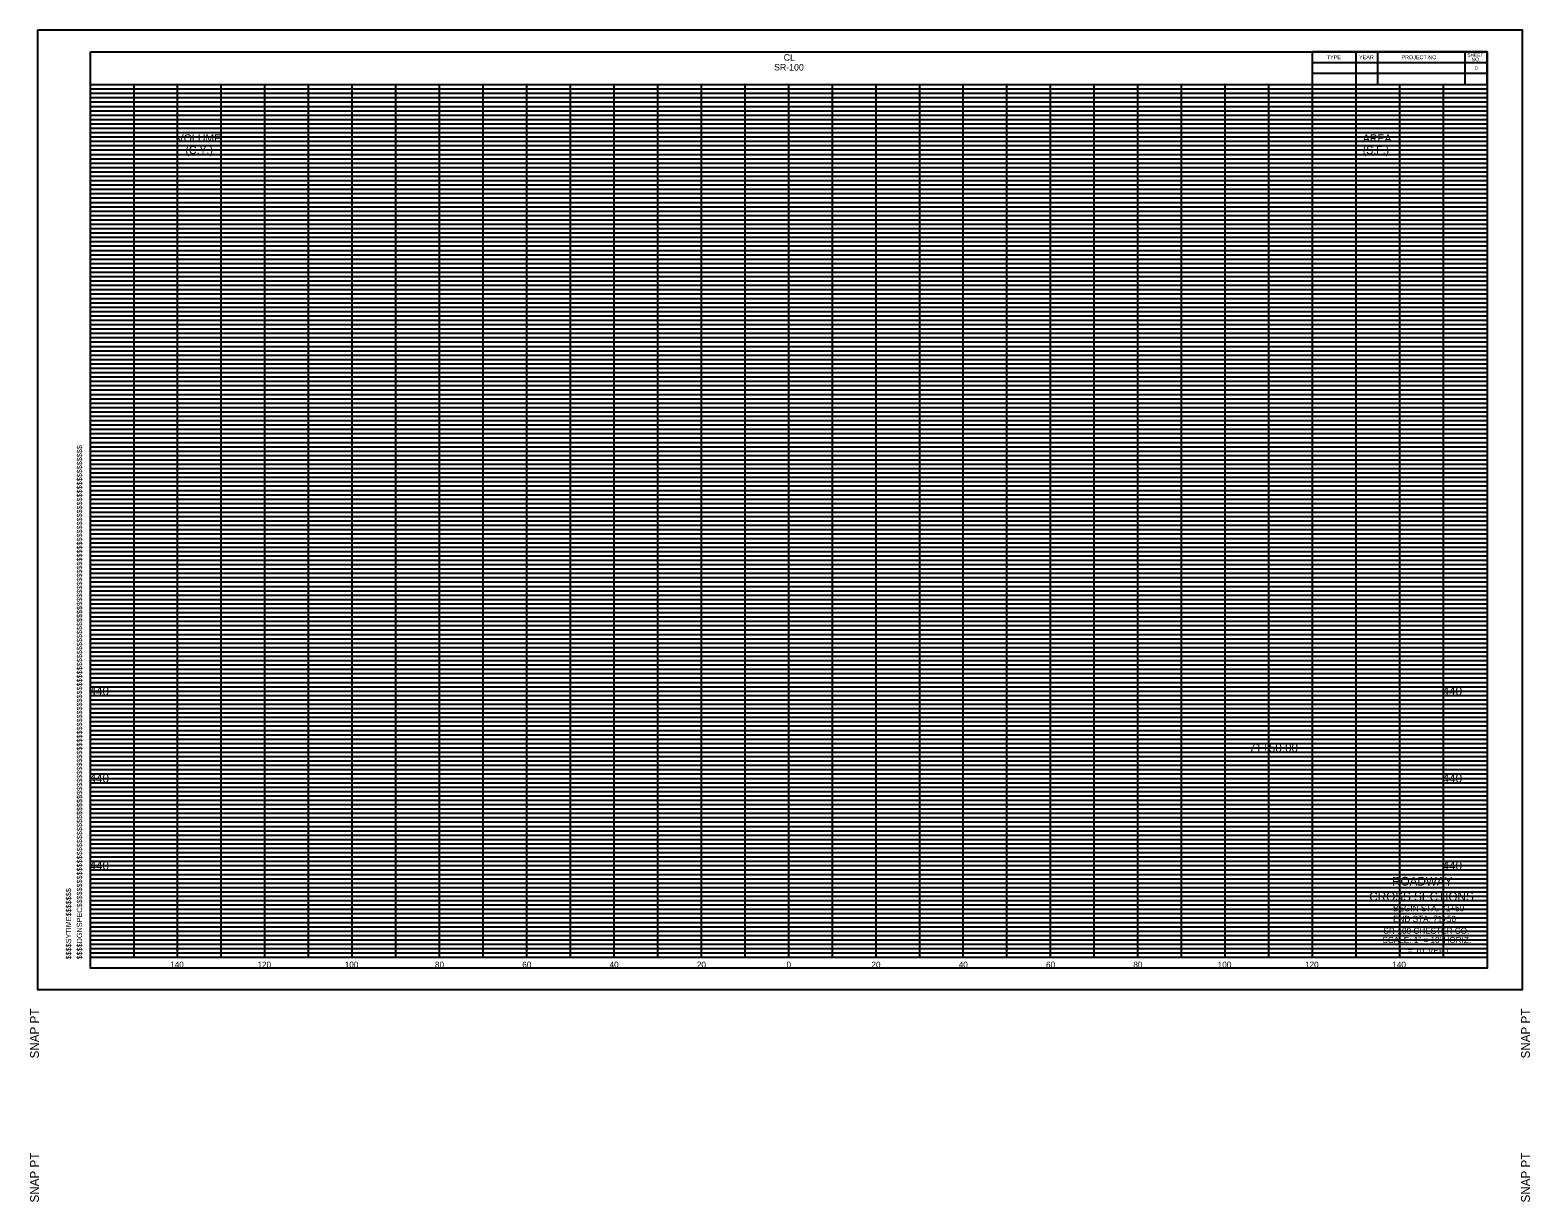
# Model space of a CAD drawing. Extents: x 37 to 1710, y 707 to 2305.
# Drawn here: x 1366.2 to 1709.8, y 2023.9 to 2292.5 of the extents above; entities that cross this region are included whole.
import ezdxf

# ---------------------------------------------------------------- set-up
doc = ezdxf.new("R2010")
doc.units = 0
for name, color, linetype in [('DESIGN - DRAINAGE - Special Ditch Width Text', 7, 'Continuous'), ('DESIGN - SHEET - Corner Text', 7, 'Continuous'), ('DESIGN - SHEET - Light Grid', 7, 'Continuous'), ('DESIGN - SHEET - Linework', 7, 'Continuous'), ('DESIGN - TYPICAL - Text', 7, 'Continuous')]:
    doc.layers.add(name, color=color, linetype=linetype)

msp = doc.modelspace()

# ---------------------------------------------------------------- linework, layer by layer
at = {"layer": 'DESIGN - SHEET - Light Grid'}
for p, q in [((1380, 2279), (1700, 2279)), ((1380, 2278), (1700, 2278)), ((1380, 2277), (1700, 2277)), ((1380, 2276), (1700, 2276)), ((1380, 2275), (1700, 2275)), ((1380, 2274), (1700, 2274)), ((1380, 2273), (1700, 2273)), ((1380, 2272), (1700, 2272)), ((1380, 2271), (1700, 2271)), ((1380, 2269), (1700, 2269)), ((1380, 2268), (1700, 2268)), ((1380, 2267), (1700, 2267)), ((1380, 2266), (1700, 2266)), ((1380, 2265), (1700, 2265)), ((1380, 2264), (1700, 2264)), ((1380, 2263), (1700, 2263)), ((1380, 2262), (1700, 2262)), ((1380, 2261), (1700, 2261)), ((1380, 2259), (1700, 2259)), ((1380, 2258), (1700, 2258)), ((1380, 2257), (1700, 2257)), ((1380, 2256), (1700, 2256)), ((1380, 2255), (1700, 2255)), ((1380, 2254), (1700, 2254)), ((1380, 2253), (1700, 2253)), ((1380, 2252), (1700, 2252)), ((1380, 2251), (1700, 2251)), ((1380, 2249), (1700, 2249)), ((1380, 2248), (1700, 2248)), ((1380, 2247), (1700, 2247)), ((1380, 2246), (1700, 2246)), ((1380, 2245), (1700, 2245)), ((1380, 2244), (1700, 2244)), ((1380, 2243), (1700, 2243)), ((1380, 2242), (1700, 2242)), ((1380, 2241), (1700, 2241)), ((1380, 2239), (1700, 2239)), ((1380, 2238), (1700, 2238)), ((1380, 2237), (1700, 2237)), ((1380, 2236), (1700, 2236)), ((1380, 2235), (1700, 2235)), ((1380, 2234), (1700, 2234)), ((1380, 2233), (1700, 2233)), ((1380, 2232), (1700, 2232)), ((1380, 2231), (1700, 2231)), ((1380, 2229), (1700, 2229)), ((1380, 2228), (1700, 2228)), ((1380, 2227), (1700, 2227)), ((1380, 2226), (1700, 2226)), ((1380, 2225), (1700, 2225)), ((1380, 2224), (1700, 2224)), ((1380, 2223), (1700, 2223)), ((1380, 2222), (1700, 2222)), ((1380, 2221), (1700, 2221)), ((1380, 2219), (1700, 2219)), ((1380, 2218), (1700, 2218)), ((1380, 2217), (1700, 2217)), ((1380, 2216), (1700, 2216)), ((1380, 2215), (1700, 2215)), ((1380, 2214), (1700, 2214)), ((1380, 2213), (1700, 2213)), ((1380, 2212), (1700, 2212)), ((1380, 2211), (1700, 2211)), ((1380, 2209), (1700, 2209)), ((1380, 2208), (1700, 2208)), ((1380, 2207), (1700, 2207)), ((1380, 2206), (1700, 2206)), ((1380, 2205), (1700, 2205)), ((1380, 2204), (1700, 2204)), ((1380, 2203), (1700, 2203)), ((1380, 2202), (1700, 2202)), ((1380, 2201), (1700, 2201)), ((1380, 2199), (1700, 2199)), ((1380, 2198), (1700, 2198)), ((1380, 2197), (1700, 2197)), ((1380, 2196), (1700, 2196)), ((1380, 2195), (1700, 2195)), ((1380, 2194), (1700, 2194)), ((1380, 2193), (1700, 2193)), ((1380, 2192), (1700, 2192)), ((1380, 2191), (1700, 2191)), ((1380, 2189), (1700, 2189)), ((1380, 2188), (1700, 2188)), ((1380, 2187), (1700, 2187)), ((1380, 2186), (1700, 2186)), ((1380, 2185), (1700, 2185)), ((1380, 2184), (1700, 2184)), ((1380, 2183), (1700, 2183)), ((1380, 2182), (1700, 2182)), ((1380, 2181), (1700, 2181)), ((1380, 2179), (1700, 2179)), ((1380, 2178), (1700, 2178)), ((1380, 2177), (1700, 2177)), ((1380, 2176), (1700, 2176)), ((1380, 2175), (1700, 2175)), ((1380, 2174), (1700, 2174)), ((1380, 2173), (1700, 2173)), ((1380, 2172), (1700, 2172)), ((1380, 2171), (1700, 2171)), ((1380, 2169), (1700, 2169)), ((1380, 2168), (1700, 2168)), ((1380, 2167), (1700, 2167)), ((1380, 2166), (1700, 2166)), ((1380, 2165), (1700, 2165)), ((1380, 2164), (1700, 2164)), ((1380, 2163), (1700, 2163)), ((1380, 2162), (1700, 2162)), ((1380, 2161), (1700, 2161)), ((1380, 2159), (1700, 2159)), ((1380, 2158), (1700, 2158)), ((1380, 2157), (1700, 2157)), ((1380, 2156), (1700, 2156)), ((1380, 2155), (1700, 2155)), ((1380, 2154), (1700, 2154)), ((1380, 2153), (1700, 2153)), ((1380, 2152), (1700, 2152)), ((1380, 2151), (1700, 2151)), ((1380, 2149), (1700, 2149)), ((1380, 2148), (1700, 2148)), ((1380, 2147), (1700, 2147)), ((1380, 2146), (1700, 2146)), ((1380, 2145), (1700, 2145)), ((1380, 2144), (1700, 2144)), ((1380, 2143), (1700, 2143)), ((1380, 2142), (1700, 2142)), ((1380, 2141), (1700, 2141)), ((1380, 2139), (1700, 2139)), ((1380, 2138), (1700, 2138)), ((1380, 2137), (1700, 2137)), ((1380, 2136), (1700, 2136)), ((1380, 2135), (1700, 2135)), ((1380, 2134), (1700, 2134)), ((1380, 2133), (1700, 2133)), ((1380, 2132), (1700, 2132)), ((1380, 2131), (1700, 2131)), ((1380, 2129), (1700, 2129)), ((1380, 2128), (1700, 2128)), ((1380, 2127), (1700, 2127)), ((1380, 2126), (1700, 2126)), ((1380, 2125), (1700, 2125)), ((1380, 2124), (1700, 2124)), ((1380, 2123), (1700, 2123)), ((1380, 2122), (1700, 2122)), ((1380, 2121), (1700, 2121)), ((1380, 2119), (1700, 2119)), ((1380, 2118), (1700, 2118)), ((1380, 2117), (1700, 2117)), ((1380, 2116), (1700, 2116)), ((1380, 2115), (1700, 2115)), ((1380, 2114), (1700, 2114)), ((1380, 2113), (1700, 2113)), ((1380, 2112), (1700, 2112)), ((1380, 2111), (1700, 2111)), ((1380, 2109), (1700, 2109)), ((1380, 2108), (1700, 2108)), ((1380, 2107), (1700, 2107)), ((1380, 2106), (1700, 2106)), ((1380, 2105), (1700, 2105)), ((1380, 2104), (1700, 2104)), ((1380, 2103), (1700, 2103)), ((1380, 2102), (1700, 2102)), ((1380, 2101), (1700, 2101)), ((1380, 2099), (1700, 2099)), ((1380, 2098), (1700, 2098)), ((1380, 2097), (1700, 2097)), ((1380, 2096), (1700, 2096)), ((1380, 2095), (1700, 2095)), ((1380, 2094), (1700, 2094)), ((1380, 2093), (1700, 2093)), ((1380, 2092), (1700, 2092)), ((1380, 2091), (1700, 2091)), ((1380, 2089), (1700, 2089)), ((1380, 2088), (1700, 2088)), ((1380, 2087), (1700, 2087)), ((1380, 2086), (1700, 2086)), ((1380, 2085), (1700, 2085)), ((1380, 2084), (1700, 2084)), ((1380, 2083), (1700, 2083)), ((1380, 2082), (1700, 2082)), ((1380, 2081), (1700, 2081))]:
    msp.add_line(p, q, dxfattribs=at)
at = {"layer": 'DESIGN - SHEET - Linework'}
for p, q in [((1700, 2287.5), (1660, 2287.5)), ((1660, 2280), (1660, 2287.5)), ((1670, 2280), (1670, 2287.5)), ((1675, 2280), (1675, 2287.5)), ((1695, 2280), (1695, 2287.5)), ((1700, 2280), (1700, 2287.5)), ((1700, 2285), (1660, 2285)), ((1700, 2282.5), (1660, 2282.5)), ((1380, 2280), (1700, 2280)), ((1390, 2080), (1390, 2280)), ((1400, 2080), (1400, 2280)), ((1410, 2080), (1410, 2280)), ((1420, 2080), (1420, 2280)), ((1430, 2080), (1430, 2280)), ((1440, 2080), (1440, 2280)), ((1450, 2080), (1450, 2280)), ((1460, 2080), (1460, 2280)), ((1470, 2080), (1470, 2280)), ((1480, 2080), (1480, 2280)), ((1490, 2080), (1490, 2280)), ((1500, 2080), (1500, 2280)), ((1510, 2080), (1510, 2280)), ((1520, 2080), (1520, 2280)), ((1530, 2080), (1530, 2280)), ((1540, 2080), (1540, 2280)), ((1550, 2080), (1550, 2280)), ((1560, 2080), (1560, 2280)), ((1570, 2080), (1570, 2280)), ((1580, 2080), (1580, 2280)), ((1590, 2080), (1590, 2280)), ((1600, 2080), (1600, 2280)), ((1610, 2080), (1610, 2280)), ((1620, 2080), (1620, 2280)), ((1630, 2080), (1630, 2280)), ((1640, 2080), (1640, 2280)), ((1650, 2080), (1650, 2280)), ((1660, 2080), (1660, 2280)), ((1670, 2080), (1670, 2280)), ((1680, 2080), (1680, 2280)), ((1690, 2080), (1690, 2280)), ((1380, 2270), (1700, 2270)), ((1380, 2260), (1700, 2260)), ((1380, 2250), (1700, 2250)), ((1380, 2240), (1700, 2240)), ((1380, 2230), (1700, 2230)), ((1380, 2220), (1700, 2220)), ((1380, 2210), (1700, 2210)), ((1380, 2200), (1700, 2200)), ((1380, 2190), (1700, 2190)), ((1380, 2180), (1700, 2180)), ((1380, 2170), (1700, 2170)), ((1380, 2160), (1700, 2160)), ((1380, 2150), (1700, 2150)), ((1380, 2140), (1700, 2140)), ((1380, 2130), (1700, 2130)), ((1380, 2120), (1700, 2120)), ((1380, 2110), (1700, 2110)), ((1380, 2100), (1700, 2100)), ((1380, 2090), (1700, 2090)), ((1380, 2080), (1700, 2080))]:
    msp.add_line(p, q, dxfattribs=at)
for points in [[(1368, 2292.5), (1708, 2292.5), (1708, 2072.5), (1368, 2072.5)], [(1380, 2287.5), (1700, 2287.5), (1700, 2077.5), (1380, 2077.5)]]:
    msp.add_lwpolyline(points, close=True, dxfattribs=at)

# ---------------------------------------------------------------- texts
at = {"layer": 'DESIGN - DRAINAGE - Special Ditch Width Text'}
for s, p in [('CL', (1538.85, 2285.46)), ('SR-100', (1536.64, 2283.23))]:
    msp.add_text(s, height=1.5, rotation=359.6675, dxfattribs=at).set_placement(p)
at = {"layer": 'DESIGN - SHEET - Corner Text'}
for s, height, p in [('0', 0.8, (1697.22, 2283.35)), ('ROADWAY ', 2, (1678.23, 2096.42)), ('CROSS SECTIONS', 2, (1673.01, 2092.92)), ('BEGIN STA. 71+50', 1.4, (1678.47, 2090.55)), ('END STA. 71+50', 1.4, (1678.47, 2088.1)), ('SR-100 CHESTER CO.', 1.4, (1676.25, 2085.37)), ('SCALE: 1" = 10\' HORIZ.', 1.4, (1676.02, 2083.26)), ('       1" = 10\' VERT.   ', 1.4, (1676.02, 2080.81))]:
    msp.add_text(s, height=height, dxfattribs=at).set_placement(p)
for s, height, p in [('$$$$DGNSPEC$$$$$$$$$$$$$$$$$$$$$$$$$$$$$$$$$$$$$$$$$$$$$$$$$$$$$$$$$$$$$$$$$$$$$$$$$$$$$$$$$$$$$$$$$$$$$$$$$$$$$$$$$$$$$$$$$$$', 1.2, (1378.1, 2079.5)), ('$$$$SYTIME$$$$$$$', 1.2, (1375.6, 2079.5)), ('SNAP PT  ', 2, (1368.2, 2056.8)), ('SNAP PT  ', 2, (1709.8, 2056.8)), ('  SNAP PT', 2, (1368.2, 2022.3)), ('  SNAP PT', 2, (1709.8, 2022.3))]:
    msp.add_text(s, height=height, rotation=90, dxfattribs=at).set_placement(p)
at = {"layer": 'DESIGN - SHEET - Light Grid'}
for s, height, p in [('TYPE', 0.9, (1663.26, 2285.8)), ('YEAR', 0.9, (1670.66, 2285.8)), ('PROJECT NO.', 0.9, (1680.38, 2285.8)), ('SHEET', 0.8, (1695.47, 2286.35)), ('NO.', 0.8, (1696.47, 2285.35))]:
    msp.add_text(s, height=height, dxfattribs=at).set_placement(p)
at = {"layer": 'DESIGN - TYPICAL - Text'}
for s, height, p in [('VOLUME', 1.8, (1399.79, 2266.79)), ('AREA ', 1.8, (1671.52, 2266.79)), ('   (C.Y.)', 1.8, (1399.79, 2264.09)), ('(S.F.)', 1.8, (1671.52, 2264.09)), ('     440     ', 2, (1376.09, 2140)), ('     440     ', 2, (1686.09, 2140)), ('71+50.00', 2, (1645.45, 2127.01)), ('     440     ', 2, (1376.09, 2120)), ('     440     ', 2, (1686.09, 2120)), ('     440     ', 2, (1376.09, 2100)), ('     440     ', 2, (1686.09, 2100)), ('     140     ', 1.4, (1395.68, 2077.6)), ('     120     ', 1.4, (1415.68, 2077.6)), ('     100     ', 1.4, (1435.68, 2077.6)), ('     80     ', 1.4, (1456.35, 2077.6)), ('     60     ', 1.4, (1476.35, 2077.6)), ('     40     ', 1.4, (1496.35, 2077.6)), ('     20     ', 1.4, (1516.35, 2077.6)), ('     0     ', 1.4, (1536.9, 2077.6)), ('     0     ', 1.4, (1536.9, 2077.6)), ('     20     ', 1.4, (1556.35, 2077.6)), ('     40     ', 1.4, (1576.35, 2077.6)), ('     60     ', 1.4, (1596.35, 2077.6)), ('     80     ', 1.4, (1616.35, 2077.6)), ('     100     ', 1.4, (1635.68, 2077.6)), ('     120     ', 1.4, (1655.68, 2077.6)), ('     140     ', 1.4, (1675.68, 2077.6))]:
    msp.add_text(s, height=height, dxfattribs=at).set_placement(p)

doc.saveas('drawing.dxf')
